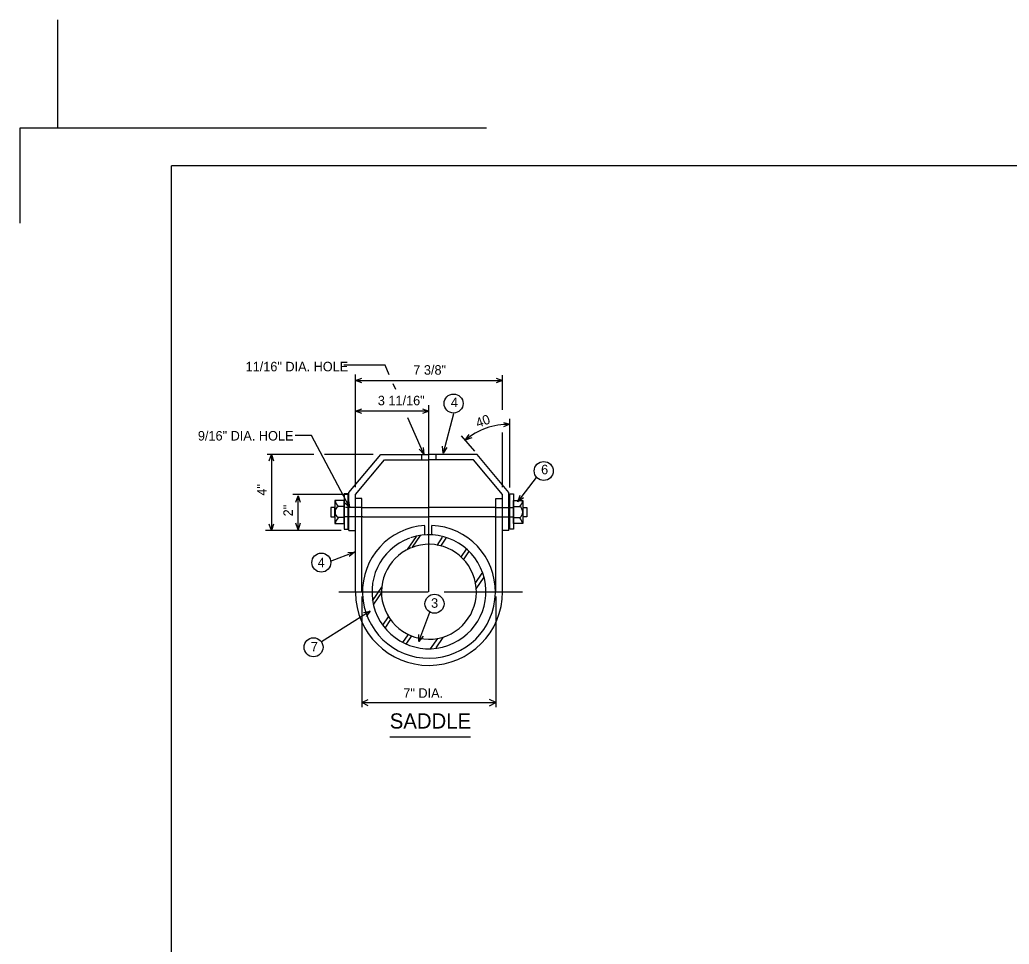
# Model space of a CAD drawing. Extents: x 15000 to 15012.1, y 999.8 to 1007.9.
# Drawn here: x 15000.392 to 15004.734, y 1003.866 to 1007.923 of the extents above; entities that cross this region are included whole.
import ezdxf

# ---------------------------------------------------------------- set-up
doc = ezdxf.new("R2010")
doc.units = 0
doc.layers.add('Level 1', color=7, linetype='Continuous')
doc.layers.add('Level 2', color=7, linetype='Continuous')

msp = doc.modelspace()

# ---------------------------------------------------------------- linework, layer by layer
at = {"layer": 'Level 1'}
for p, q in [((15002.44, 1007.4479), (15000.3918, 1007.4479)), ((15000.3918, 1007.4479), (15000.3918, 1007.0308)), ((15001.0578, 1000.2885), (15001.0578, 1007.2814)), ((15011.5058, 1007.2814), (15001.0578, 1007.2814))]:
    msp.add_line(p, q, dxfattribs=at)
at = {"layer": 'Level 2'}
for p, q in [((15000.5583, 1007.4479), (15000.5583, 1007.9229)), ((15001.9948, 1006.4077), (15001.814, 1006.4077)), ((15002.0132, 1006.3651), (15001.9948, 1006.4077)), ((15001.8643, 1005.8723), (15001.8643, 1006.3656)), ((15002.5102, 1006.2106), (15002.5102, 1006.3634)), ((15001.8643, 1006.3399), (15001.8925, 1006.3497)), ((15001.8643, 1006.3399), (15002.5102, 1006.3399)), ((15001.8925, 1006.3302), (15001.8643, 1006.3399)), ((15002.0415, 1006.2998), (15002.0303, 1006.3258)), ((15002.482, 1006.3497), (15002.5102, 1006.3399)), ((15002.5102, 1006.3399), (15002.482, 1006.3302)), ((15001.8643, 1005.8723), (15001.8643, 1006.2389)), ((15002.1873, 1005.4127), (15002.1873, 1006.2312)), ((15001.8643, 1006.2056), (15001.8925, 1006.2153)), ((15002.1873, 1006.2056), (15001.8643, 1006.2056)), ((15001.8925, 1006.1958), (15001.8643, 1006.2056)), ((15002.1591, 1006.2153), (15002.1873, 1006.2056)), ((15002.1873, 1006.2056), (15002.1591, 1006.1958)), ((15002.2958, 1006.1942), (15002.2493, 1006.0217)), ((15002.1644, 1006.0162), (15002.0951, 1006.1762)), ((15002.5138, 1006.1563), (15002.5423, 1006.1476)), ((15002.5423, 1006.1476), (15002.5144, 1006.1368)), ((15002.543, 1005.8697), (15002.543, 1006.1723)), ((15001.6717, 1006.0983), (15001.6005, 1006.0983)), ((15001.8387, 1005.7835), (15001.6717, 1006.0983)), ((15002.3889, 1006.0299), (15002.3308, 1006.0974)), ((15002.3468, 1006.0785), (15002.3632, 1006.1033)), ((15002.5102, 1005.8723), (15002.5102, 1006.112)), ((15002.2493, 1006.0217), (15002.2473, 1006.0514)), ((15002.375, 1006.0879), (15002.3468, 1006.0785)), ((15001.6826, 1006.0153), (15001.4773, 1006.0153)), ((15001.486, 1005.9872), (15001.4958, 1006.0153)), ((15001.4958, 1006.0153), (15001.4958, 1005.682)), ((15001.4958, 1006.0153), (15001.5055, 1005.9872)), ((15001.9425, 1006.0153), (15001.7292, 1006.0153)), ((15001.8359, 1005.8487), (15001.9758, 1006.0153)), ((15001.9758, 1006.0153), (15002.1873, 1006.0153)), ((15002.1644, 1006.0162), (15002.1443, 1006.0382)), ((15002.1558, 1005.9923), (15002.1558, 1006.0137)), ((15002.1622, 1006.0459), (15002.1644, 1006.0162)), ((15002.3987, 1006.0153), (15002.1873, 1006.0153)), ((15002.2187, 1005.9923), (15002.2187, 1006.0137)), ((15002.2661, 1006.0463), (15002.2493, 1006.0217)), ((15002.5386, 1005.8487), (15002.3987, 1006.0153)), ((15001.8643, 1005.839), (15001.9921, 1005.9913)), ((15001.9921, 1005.9913), (15002.1873, 1005.9913)), ((15002.3824, 1005.9913), (15002.1873, 1005.9913)), ((15002.5102, 1005.839), (15002.3824, 1005.9913)), ((15002.5778, 1005.8082), (15002.6599, 1005.9149)), ((15001.831, 1005.839), (15001.5895, 1005.839)), ((15001.6033, 1005.8063), (15001.613, 1005.8344)), ((15001.613, 1005.6851), (15001.613, 1005.8344)), ((15001.613, 1005.8344), (15001.6228, 1005.8063)), ((15001.8359, 1005.682), (15001.8359, 1005.8487)), ((15001.8643, 1005.4127), (15001.8643, 1005.839)), ((15002.5102, 1005.4127), (15002.5102, 1005.839)), ((15002.5386, 1005.682), (15002.5386, 1005.8487)), ((15002.5778, 1005.8082), (15002.5873, 1005.8364)), ((15001.8387, 1005.7835), (15001.8168, 1005.8038)), ((15001.8387, 1005.7835), (15001.8168, 1005.8038)), ((15001.8341, 1005.8129), (15001.8387, 1005.7835)), ((15001.8341, 1005.8129), (15001.8387, 1005.7835)), ((15001.8933, 1005.8228), (15001.8643, 1005.8228)), ((15001.8933, 1005.4127), (15001.8933, 1005.8228)), ((15002.4812, 1005.4127), (15002.4812, 1005.8228)), ((15002.4812, 1005.8228), (15002.5102, 1005.8228)), ((15002.6028, 1005.8246), (15002.5778, 1005.8082)), ((15001.8154, 1005.7868), (15001.7883, 1005.7868)), ((15001.8935, 1005.7828), (15001.8208, 1005.7828)), ((15001.8935, 1005.7828), (15002.1847, 1005.7828)), ((15002.481, 1005.7828), (15002.1898, 1005.7828)), ((15002.481, 1005.7828), (15002.5537, 1005.7828)), ((15002.5591, 1005.7868), (15002.5863, 1005.7868)), ((15001.4958, 1005.682), (15001.486, 1005.7102)), ((15001.5055, 1005.7102), (15001.4958, 1005.682)), ((15001.613, 1005.6851), (15001.6033, 1005.7133)), ((15001.6228, 1005.7133), (15001.613, 1005.6851)), ((15001.8156, 1005.738), (15001.7886, 1005.738)), ((15001.8978, 1005.7411), (15001.8198, 1005.7411)), ((15001.8978, 1005.7411), (15002.1889, 1005.7411)), ((15002.4768, 1005.7411), (15002.1856, 1005.7411)), ((15002.1999, 1005.6648), (15002.1999, 1005.7038)), ((15002.4768, 1005.7411), (15002.5547, 1005.7411)), ((15002.5589, 1005.738), (15002.5859, 1005.738)), ((15001.8026, 1005.682), (15001.4702, 1005.682)), ((15001.8359, 1005.682), (15001.8648, 1005.682)), ((15002.1698, 1005.6623), (15002.1698, 1005.7026)), ((15002.5386, 1005.682), (15002.5097, 1005.682)), ((15002.0935, 1005.5986), (15002.1322, 1005.6554)), ((15002.1158, 1005.6084), (15002.1506, 1005.6595)), ((15002.2228, 1005.6163), (15002.2471, 1005.652)), ((15002.2396, 1005.6127), (15002.2636, 1005.6479)), ((15001.8606, 1005.5864), (15001.7538, 1005.5453)), ((15001.8308, 1005.5854), (15001.8606, 1005.5864)), ((15001.8606, 1005.5864), (15001.8378, 1005.5672)), ((15002.3295, 1005.5672), (15002.3518, 1005.6)), ((15002.3391, 1005.5528), (15002.3628, 1005.5877)), ((15002.39, 1005.4495), (15002.4203, 1005.4939)), ((15002.3951, 1005.4258), (15002.4298, 1005.4768)), ((15001.7923, 1005.4127), (15002.1836, 1005.4127)), ((15001.9398, 1005.3728), (15001.9808, 1005.433)), ((15001.9458, 1005.3588), (15001.9807, 1005.4099)), ((15002.2548, 1005.4127), (15002.5985, 1005.4127)), ((15001.8933, 1005.3918), (15001.8933, 1004.9058)), ((15002.4812, 1005.3918), (15002.4812, 1004.9058)), ((15001.9299, 1005.3279), (15001.7152, 1005.1931)), ((15001.9008, 1005.3212), (15001.9299, 1005.3279)), ((15001.9299, 1005.3279), (15001.9113, 1005.3047)), ((15002.1425, 1005.1949), (15002.1918, 1005.3236)), ((15001.9845, 1005.2663), (15002.0093, 1005.3028)), ((15001.9948, 1005.2531), (15002.0203, 1005.2904)), ((15002.0729, 1005.1903), (15002.0962, 1005.2245)), ((15002.0875, 1005.1834), (15002.1118, 1005.2191)), ((15002.1425, 1005.1949), (15002.1435, 1005.2248)), ((15002.1617, 1005.2178), (15002.1425, 1005.1949)), ((15002.1948, 1005.1628), (15002.2258, 1005.2082)), ((15002.2185, 1005.1663), (15002.2496, 1005.2121)), ((15001.8933, 1004.9267), (15002.4812, 1004.9267)), ((15002.0154, 1004.7761), (15002.3702, 1004.7761))]:
    msp.add_line(p, q, dxfattribs=at)
for points in [[(15001.8158, 1005.843), (15001.8158, 1005.6877), (15001.8328, 1005.6877), (15001.8328, 1005.843)], [(15002.5588, 1005.843), (15002.5588, 1005.6877), (15002.5418, 1005.6877), (15002.5418, 1005.843)], [(15001.7749, 1005.8137), (15001.7749, 1005.712), (15001.8154, 1005.712), (15001.8154, 1005.8137)], [(15002.5996, 1005.8137), (15002.5996, 1005.712), (15002.5591, 1005.712), (15002.5591, 1005.8137)], [(15001.7574, 1005.7833), (15001.7574, 1005.7413), (15001.7744, 1005.7413), (15001.7744, 1005.7833)], [(15002.6171, 1005.7833), (15002.6171, 1005.7413), (15002.6001, 1005.7413), (15002.6001, 1005.7833)]]:
    msp.add_lwpolyline(points, close=True, dxfattribs=at)
for points in [[(15001.9211, 1004.9128), (15001.8933, 1004.9267), (15001.9211, 1004.9406)], [(15002.4534, 1004.9128), (15002.4812, 1004.9267), (15002.4534, 1004.9406)]]:
    msp.add_lwpolyline(points, dxfattribs=at)
for centre in [(15002.2955, 1006.2389), (15002.6909, 1005.9428), (15001.7151, 1005.5408), (15002.2117, 1005.3602), (15001.681, 1005.1692)]:
    msp.add_circle(centre, 0.0417, dxfattribs=at)
for centre, radius, start, end in [((15002.5368, 1005.8519), 0.2957, 88.9343, 129.9748), ((15001.8253, 1005.8219), 0.0505, 189.7316, 223.892), ((15002.5492, 1005.8219), 0.0505, 316.108, 350.2684), ((15001.8047, 1005.7624), 0.0293, 123.2073, 236.7942), ((15002.5698, 1005.7624), 0.0293, 303.2058, 56.7927), ((15001.864, 1005.6826), 0.0936, 143.7834, 161.7531), ((15002.1873, 1005.4127), 0.2917, 93.4543, 87.5112), ((15002.5105, 1005.6826), 0.0936, 18.2469, 36.2166), ((15002.1873, 1005.4127), 0.25, 109.9994, 108.8965), ((15002.1873, 1005.4127), 0.2083, 112.6357, 111.6919), ((15002.1873, 1005.4127), 0.3229, 180.6706, 0)]:
    msp.add_arc(centre, radius, start, end, dxfattribs=at)

# ---------------------------------------------------------------- texts
for s, height, p in [('11/16" DIA. HOLE', 0.041667, (15001.3828, 1006.3803)), ('7 3/8"', 0.04167, (15002.1187, 1006.3655)), ('3 11/16"', 0.04167, (15001.963, 1006.2312)), ('4', 0.0417, (15002.2834, 1006.2232)), ('9/16" DIA. HOLE', 0.041667, (15001.1734, 1006.0765)), ('6', 0.0417, (15002.6796, 1005.9285)), ('4', 0.0417, (15001.699, 1005.5203)), ('3', 0.0417, (15002.1967, 1005.3426)), ('7', 0.0417, (15001.6689, 1005.1509)), (' 7" DIA. ', 0.04167, (15002.0594, 1004.9475)), ('SADDLE', 0.06667, (15002.0154, 1004.8125))]:
    msp.add_text(s, height=height, dxfattribs=at).set_placement(p)
for s, rotation, p in [('40', 20.065, (15002.4018, 1006.1319)), ('4"', 90, (15001.4749, 1005.8347)), ('2"', 90, (15001.5901, 1005.7437))]:
    msp.add_text(s, height=0.04167, rotation=rotation, dxfattribs=at).set_placement(p)

doc.saveas('drawing.dxf')
